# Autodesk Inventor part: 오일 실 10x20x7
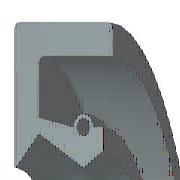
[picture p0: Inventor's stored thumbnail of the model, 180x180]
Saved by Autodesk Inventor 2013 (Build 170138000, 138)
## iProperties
IsCustomPart: 1
Created: 2012-02
Part Number: 오일 실 10x20x7
Material: 고무
Description: 오일-실
Document SubType Name: Modeling
Standard: KS B 2804
Designer: mduedu
Standards Organization: KS
Language: ko-KR
Size Designation: D - 10 20 7
Categories: <MemberInstance><Categories><Category DisplayName="샤프트 부품" InternalName="7f7aeb1f-a693-4053-b835-cee3144e0d98" Mnemonic="SHFT"><Category DisplayName="실링" Intern
Density: 0.93 g/cm^3
Author: mduedu
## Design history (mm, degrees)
revolve "본체" stored, may be unused: angle "d17" = 90 deg
revolve "스프링1" stored, may be unused: angle "d18" = 90 deg
body "Solid1"
sketch "스케치1"
  geometry: L1 (0, 10)-(7, 10); L2 (7, 8.25)-(1.75, 8.25); L3 (1.75, 6.75)-(4.9, 5); L4 (4.9, 5)-(0, 5); L5 (0, 0)-(9.586, 0) reference; L6 (4.9, 5)-(6.3, 5.875); L7 (0, 18)-(0, -3) reference; L8 (-1.941, 0)-(11.507, 0) reference; L9 (4.2, 7.1)-(1.75, 7.59); L10 (1.75, 7.59)-(1.75, 8.25); L11 (0, 10)-(0, 5.088); L12 (4.9, 5)-(0, 5); L13 (1.75, 6.75)-(0.152, 5.028); L14 (7, 10)-(7, 8.25); L15 (5.6, 7.1)-(6.3, 7.1); L16 (6.3, 7.1)-(6.3, 5.875); C1 r 0.455 at (4.9, 7.1); A1 r 0.7 centre (4.9, 7.1) between (5.6, 7.1) and (4.2, 7.1); A2 r 0.088 centre (0.088, 5.088) between (0, 5.088) and (0.152, 5.028); 1 further point
  constraints: 28 end point, 5 horizontal alignment, 5 point on line, 4 point on circle, 4 vertical alignment, 3 centre point, 3 tangent, 2 collinear, 2 horizontal, 2 perpendicular, 1 coincident, 1 parallel
  dimensions: "d0" = 20 diameter of L1 L5 (= SD2); "d1" = 1.75 distance of L1.end L2.start (= SD); "d2" = 0.91 diameter of C1 (= SPDI); "d3" = 1.4 diameter of A1 (= SPDA); "d4" = 10 diameter of L3.end L5 (= NND); "d5" = 13.5 diameter of L3.start L5 (= TKDM); "d7" = 15.18 diameter of L9.end L5 (= TKDM + 0.24 x SWDT); "d8" = 1.75 distance between parallel lines of L11 L10 (= SD); "d9" = 4.9 distance from line of L11 C1.centre (= SPDST); "d10" = 14.2 diameter of C1.centre L5 (= HLDM); "d11" = 0.0875 radius of A2 (= 0.25 x LAB); "d12" = 6.3 distance between parallel lines of L11 L16 (= SDI); "d13" = 11.75 diameter of L6.end L5 (= ABDM); "d14" = 7 distance from line of L11 L1.end (= SWDT)
fillet "모깎기1" dims "d6" = 0.3 (= RR)
other parameters: "SD2" = 20 [user parameter; used in 1 equation term], "SWDT" = 7 [user parameter; used in 2 equation terms], "RR" = 0.3 [user parameter; used in 1 equation term], "SD" = 1.75 [user parameter; used in 2 equation terms], "NND" = 10 [user parameter; used in 1 equation term], "SPDA" = 1.4 [user parameter; used in 1 equation term], "SPDI" = 0.91 [user parameter; used in 1 equation term], "TKDM" = 13.5 [user parameter; used in 2 equation terms], "HLDM" = 14.2 [user parameter; used in 1 equation term], "ABDM" = 11.75 [user parameter; used in 1 equation term], "SDI" = 6.3 [user parameter; used in 1 equation term], "SPDST" = 4.9 [user parameter; used in 1 equation term], "LAB" = 0.35 [user parameter; used in 1 equation term], "d15" = 0, "d16" = 0, "d19" = 0
